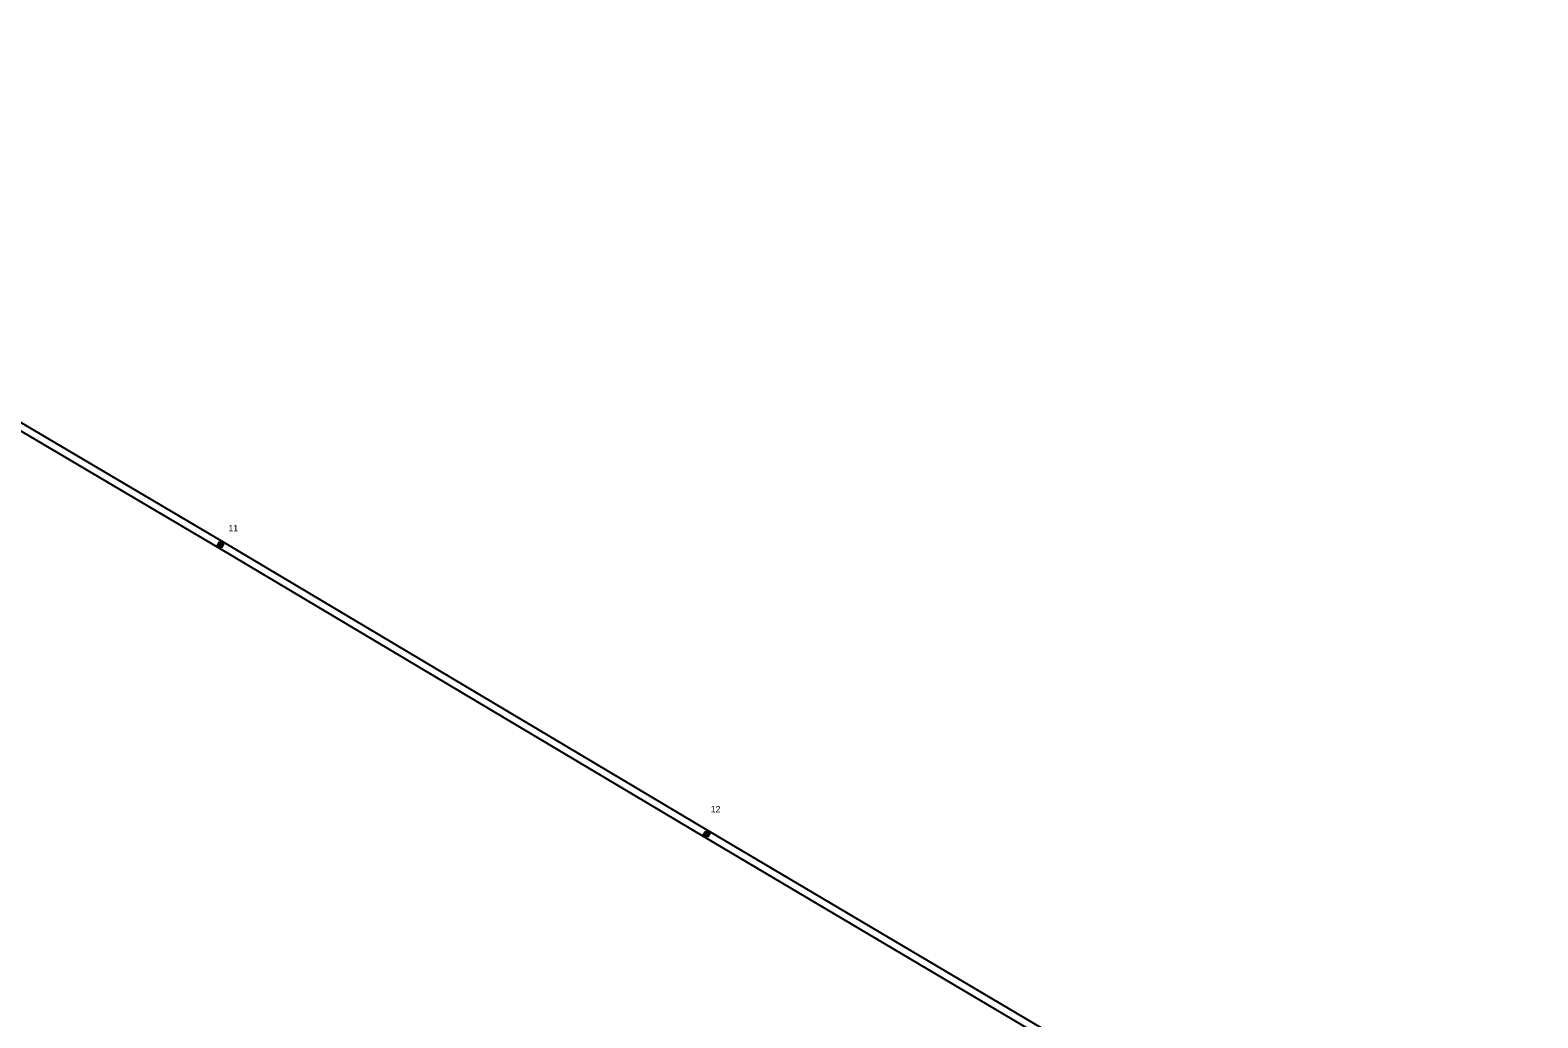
# Model space of a CAD drawing. Extents: x -545588 to -543214, y -1196037 to -1194452.
# Drawn here: x -544058.1 to -543648.4, y -1195769.2 to -1195500.9 of the extents above; entities that cross this region are included whole.
import ezdxf

# ---------------------------------------------------------------- set-up
doc = ezdxf.new("R2010")
doc.units = 0
for name, color, linetype in [('DOPLŇ_POPISY', 7, 'Continuous'), ('ELE_EON_POPIS', 7, 'Continuous'), ('Implicitní', 7, 'Continuous'), ('POL_ZNAČKA_PRACOVNÍ', 7, 'Continuous')]:
    doc.layers.add(name, color=color, linetype=linetype)

# ---------------------------------------------------------------- blocks, each defined once
blk = doc.blocks.new('VN470')
at = {"layer": 'ELE_EON_POPIS'}
for points in [[(-1.23, 1.22), (1.23, 1.22)], [(-1.23, -1.23), (-1.23, 1.22)], [(-0.92, 0.9), (0.92, 0.9)], [(-0.92, -0.95), (-0.92, 0.9)], [(-0.61, 0.61), (0.61, 0.61)], [(-0.61, -0.62), (-0.61, 0.61)], [(-0.31, -0.27), (-0.31, 0.34)], [(-0.31, 0.34), (0.31, 0.34)], [(0, 1.22), (0, 1.97)], [(0.31, 0.34), (0.31, -0.27)], [(0.61, 0.61), (0.61, -0.62)], [(0.92, 0.9), (0.92, -0.95)], [(1.23, 1.22), (1.23, -1.23)], [(1.23, -1.23), (-1.23, -1.23)], [(0.92, -0.95), (-0.92, -0.95)], [(0.61, -0.62), (-0.61, -0.62)], [(0.31, -0.27), (-0.31, -0.27)], [(0, -1.23), (0, -1.98)]]:
    blk.add_lwpolyline(points, dxfattribs=at)

msp = doc.modelspace()

# ---------------------------------------------------------------- linework, layer by layer
at = {"layer": 'Implicitní'}
for points in [[(-545089.24, -1194965.91), (-544970.24, -1195070.43), (-544834.23, -1195151.6), (-544689.66, -1195237.3), (-544557.56, -1195315.82), (-544421.64, -1195396.76), (-544281.07, -1195479.77), (-544142, -1195561.75), (-544006.84, -1195641.51), (-543874.79, -1195720.12), (-543751.48, -1195793.04), (-543649.47, -1195854.14)], [(-545087.92, -1194964.41), (-544969.06, -1195068.81), (-544833.21, -1195149.88), (-544688.64, -1195235.58), (-544556.54, -1195314.1), (-544420.62, -1195395.04), (-544280.05, -1195478.05), (-544140.98, -1195560.03), (-544005.82, -1195639.79), (-543873.77, -1195718.4), (-543750.46, -1195791.32), (-543648.45, -1195852.42)]]:
    msp.add_lwpolyline(points, dxfattribs=at)

# ---------------------------------------------------------------- block references
at = {"layer": 'DOPLŇ_POPISY', "yscale": 0.5000000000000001}
for p, xscale, rotation in [((-544006.33, -1195640.65), 0.5, 151.64060641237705), ((-543874.28, -1195719.26), 0.5000000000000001, 149.39949998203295)]:
    msp.add_blockref('VN470', p, dxfattribs=dict(at, xscale=xscale, rotation=rotation))

# ---------------------------------------------------------------- texts
at = {"layer": 'POL_ZNAČKA_PRACOVNÍ'}
for s, p in [('11', (-544004.18, -1195637.04)), ('12', (-543873.14, -1195713.36))]:
    msp.add_text(s, height=1.75, dxfattribs=at).set_placement(p)

doc.saveas('drawing.dxf')
